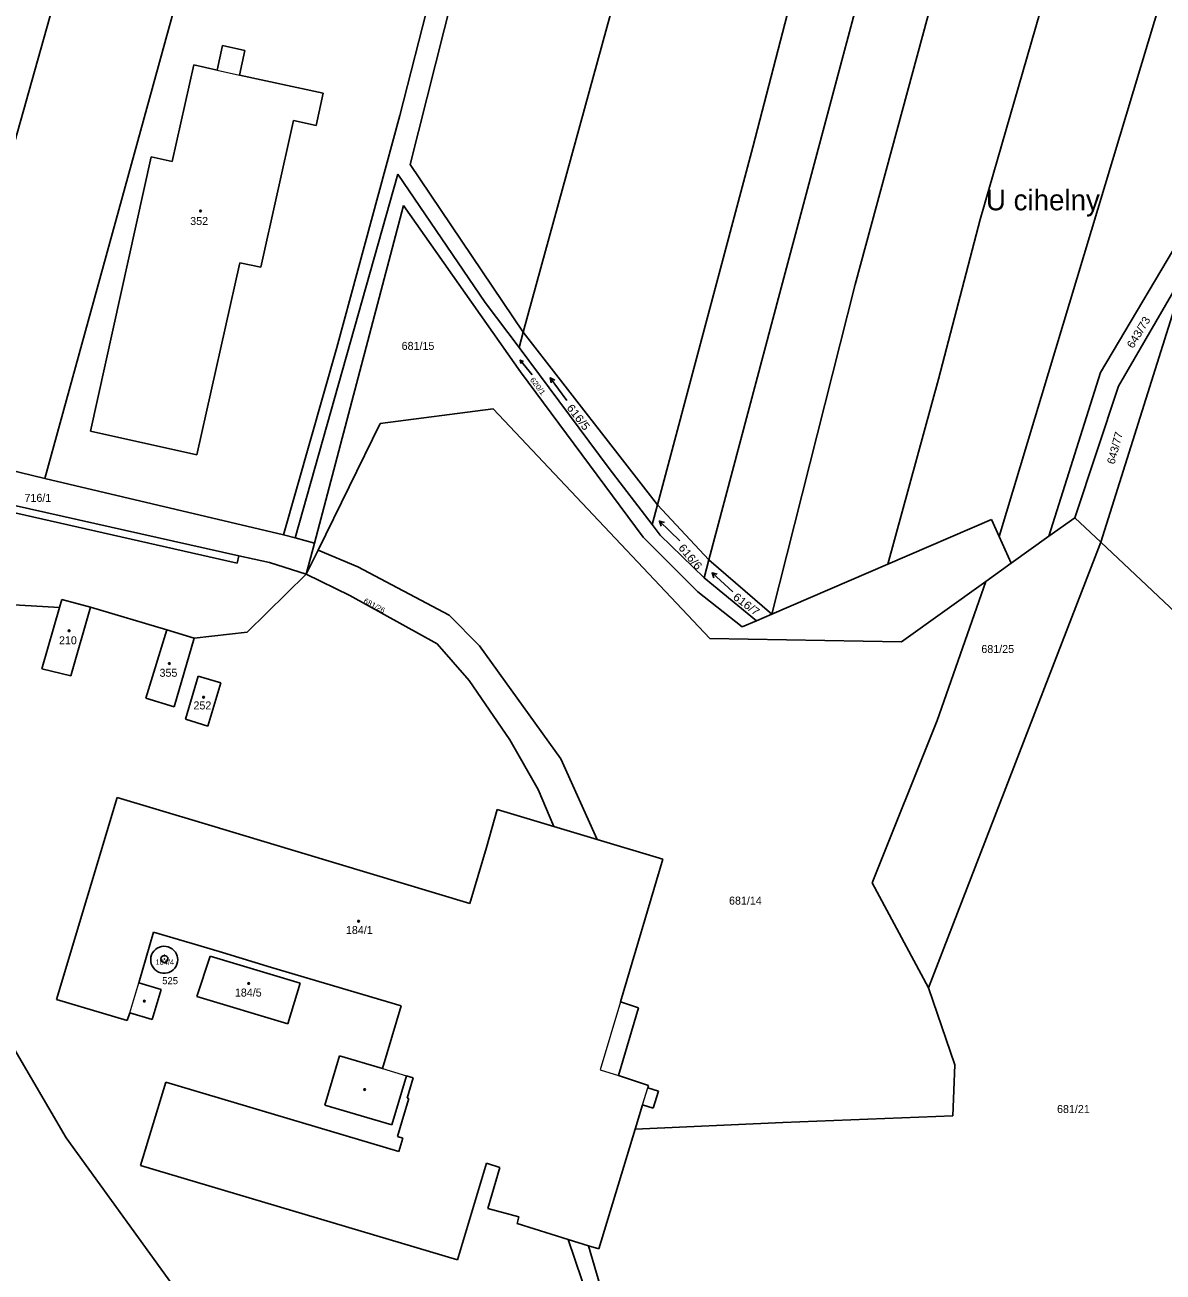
# Model space of a CAD drawing. Extents: x -701211 to -698780, y -1014269 to -1012378.
# Drawn here: x -700355.1 to -700113.3, y -1014024.8 to -1013759.8 of the extents above; entities that cross this region are included whole.
import ezdxf
from ezdxf.enums import TextEntityAlignment as Align

# ---------------------------------------------------------------- set-up
doc = ezdxf.new("R2010")
doc.units = 0
doc.header["$LTSCALE"] = 0.68
for name, color, linetype, lineweight in [('1', 7, 'Continuous', 25), ('3', 7, 'Continuous', 25), ('4', 7, 'Continuous', 13), ('5', 7, 'Continuous', 25), ('7', 7, 'Continuous', 13), ('8', 7, 'Continuous', 25)]:
    doc.layers.add(name, color=color, linetype=linetype, lineweight=lineweight)
doc.layers.add('2', color=7, linetype='Continuous')

msp = doc.modelspace()

# ---------------------------------------------------------------- linework, layer by layer
at = {"layer": '1'}
for p, q in [((-700152.11, -1013801.13), (-700103.11, -1013630.91)), ((-700375.69, -1013850.23), (-700324.49, -1013667.95)), ((-700169.53, -1013666.16), (-700200.4, -1013785.73)), ((-700300.53, -1013673.39), (-700350.86, -1013856.14)), ((-700092.33, -1013683.22), (-700148.1, -1013868.52)), ((-700275.41, -1013779.04), (-700251.21, -1013684.29)), ((-700249.19, -1013825.04), (-700213.5, -1013694.58)), ((-700273.23, -1013789.41), (-700250.03, -1013697.82)), ((-700194.71, -1013816.74), (-700166.66, -1013711.75)), ((-700178.73, -1013814.96), (-700161.98, -1013753.3)), ((-700313.1, -1013764.16), (-700314.23, -1013769.37)), ((-700308.35, -1013765.19), (-700313.1, -1013764.16)), ((-700309.49, -1013770.43), (-700308.35, -1013765.19)), ((-700319.17, -1013768.3), (-700323.76, -1013788.78)), ((-700314.23, -1013769.37), (-700319.17, -1013768.3)), ((-700291.68, -1013774.3), (-700309.49, -1013770.43)), ((-700293.21, -1013781.14), (-700291.68, -1013774.3)), ((-700288.81, -1013828.32), (-700275.41, -1013779.04)), ((-700304.97, -1013811.28), (-700298.02, -1013780.1)), ((-700298.02, -1013780.1), (-700293.21, -1013781.14)), ((-700220.71, -1013861.79), (-700200.4, -1013785.73)), ((-700328.22, -1013787.8), (-700341.16, -1013846.09)), ((-700323.76, -1013788.78), (-700328.22, -1013787.8)), ((-700249.19, -1013825.04), (-700273.23, -1013789.41)), ((-700275.83, -1013791.47), (-700297.66, -1013868.8)), ((-700275.83, -1013791.47), (-700257.26, -1013818.75)), ((-700126.55, -1013833.66), (-700102.16, -1013792.37)), ((-700293.56, -1013869.88), (-700274.66, -1013798.13)), ((-700274.66, -1013798.13), (-700249.82, -1013833.47)), ((-700160.98, -1013835.07), (-700152.11, -1013801.13)), ((-700318.53, -1013851.13), (-700309.39, -1013810.31)), ((-700309.39, -1013810.31), (-700304.97, -1013811.28)), ((-700126.53, -1013869.72), (-700108.15, -1013811.38)), ((-700122.79, -1013836.53), (-700108.15, -1013811.38)), ((-700196.42, -1013885), (-700178.73, -1013814.96)), ((-700257.26, -1013818.75), (-700250.1, -1013828.36)), ((-700209.77, -1013873.46), (-700194.71, -1013816.74)), ((-700250.1, -1013828.36), (-700249.19, -1013825.04)), ((-700249.19, -1013825.04), (-700220.71, -1013861.79)), ((-700250.1, -1013828.36), (-700230.98, -1013854.02)), ((-700249.82, -1013833.47), (-700223.72, -1013868.65)), ((-700171.79, -1013874.38), (-700160.98, -1013835.07)), ((-700137.52, -1013868.44), (-700126.55, -1013833.66)), ((-700132.06, -1013864.53), (-700122.79, -1013836.53)), ((-700255.6, -1013841.37), (-700279.57, -1013844.46)), ((-700209.56, -1013890.14), (-700255.6, -1013841.37)), ((-700292.8, -1013871.39), (-700279.57, -1013844.46)), ((-700341.16, -1013846.09), (-700318.53, -1013851.13)), ((-700350.86, -1013856.14), (-700375.69, -1013850.23)), ((-700230.98, -1013854.02), (-700221.83, -1013865.97)), ((-700374.64, -1013857.97), (-700309.64, -1013872.57)), ((-700310, -1013874.16), (-700361.05, -1013862.58)), ((-700220.71, -1013861.79), (-700221.83, -1013865.97)), ((-700220.71, -1013861.79), (-700209.77, -1013873.46)), ((-700221.83, -1013865.97), (-700220.12, -1013868.2)), ((-700149.74, -1013864.87), (-700171.79, -1013874.38)), ((-700148.1, -1013868.52), (-700149.74, -1013864.87)), ((-700132.06, -1013864.53), (-700137.52, -1013868.44)), ((-700132.06, -1013864.53), (-700126.53, -1013869.72)), ((-700300.12, -1013868.12), (-700297.66, -1013868.8)), ((-700297.66, -1013868.8), (-700293.56, -1013869.88)), ((-700223.72, -1013868.65), (-700212.15, -1013880.22)), ((-700220.12, -1013868.2), (-700210.79, -1013877.28)), ((-700145.56, -1013874.19), (-700148.1, -1013868.52)), ((-700145.56, -1013874.19), (-700137.52, -1013868.44)), ((-700295.29, -1013876.47), (-700293.56, -1013869.88)), ((-700292.8, -1013871.39), (-700295.29, -1013876.47)), ((-700292.8, -1013871.39), (-700284.36, -1013874.94)), ((-700163.11, -1013964.42), (-700126.53, -1013869.72)), ((-700109.42, -1013885.76), (-700126.53, -1013869.72)), ((-700310, -1013874.16), (-700309.64, -1013872.57)), ((-700303.08, -1013874.04), (-700309.64, -1013872.57)), ((-700295.29, -1013876.47), (-700303.08, -1013874.04)), ((-700209.77, -1013873.46), (-700210.79, -1013877.28)), ((-700209.77, -1013873.46), (-700196.42, -1013885)), ((-700171.79, -1013874.38), (-700196.42, -1013885)), ((-700150.96, -1013878.06), (-700145.56, -1013874.19)), ((-700307.85, -1013888.81), (-700295.29, -1013876.47)), ((-700295.29, -1013876.47), (-700286.04, -1013881.02)), ((-700284.36, -1013874.94), (-700264.92, -1013885.2)), ((-700210.79, -1013877.28), (-700199.69, -1013886.41)), ((-700168.85, -1013890.87), (-700150.96, -1013878.06)), ((-700150.96, -1013878.06), (-700161.28, -1013907.62)), ((-700379.57, -1013881.73), (-700347.72, -1013883.56)), ((-700347.22, -1013881.85), (-700347.72, -1013883.56)), ((-700341.12, -1013883.53), (-700347.22, -1013881.85)), ((-700267.49, -1013891.29), (-700286.04, -1013881.02)), ((-700212.15, -1013880.22), (-700202.68, -1013887.7)), ((-700347.72, -1013883.56), (-700351.49, -1013896.58)), ((-700345.28, -1013898.08), (-700341.12, -1013883.53)), ((-700341.12, -1013883.53), (-700324.93, -1013888.34)), ((-700264.92, -1013885.2), (-700258.51, -1013891.71)), ((-700196.42, -1013885), (-700199.69, -1013886.41)), ((-700199.69, -1013886.41), (-700202.68, -1013887.7)), ((-700324.93, -1013888.34), (-700329.35, -1013902.83)), ((-700319.09, -1013890.11), (-700324.93, -1013888.34)), ((-700323.37, -1013904.65), (-700319.09, -1013890.11)), ((-700319.09, -1013890.11), (-700307.85, -1013888.81)), ((-700168.85, -1013890.87), (-700209.56, -1013890.14)), ((-700260.67, -1013899.06), (-700267.49, -1013891.29)), ((-700241.19, -1013915.76), (-700258.51, -1013891.71)), ((-700351.49, -1013896.58), (-700345.28, -1013898.08)), ((-700320.98, -1013907.33), (-700318.25, -1013898.14)), ((-700313.47, -1013899.56), (-700318.25, -1013898.14)), ((-700316.22, -1013908.77), (-700313.47, -1013899.56)), ((-700252.06, -1013911.66), (-700260.67, -1013899.06)), ((-700329.35, -1013902.83), (-700323.37, -1013904.65)), ((-700320.98, -1013907.33), (-700316.22, -1013908.77)), ((-700161.28, -1013907.62), (-700175.06, -1013942.11)), ((-700246.07, -1013922.27), (-700252.06, -1013911.66)), ((-700241.19, -1013915.76), (-700233.51, -1013932.86)), ((-700242.72, -1013930.1), (-700246.07, -1013922.27)), ((-700335.47, -1013923.92), (-700348.34, -1013966.9)), ((-700335.47, -1013923.92), (-700317.48, -1013929.35)), ((-700257.03, -1013934.55), (-700254.72, -1013926.52)), ((-700254.72, -1013926.52), (-700242.72, -1013930.1)), ((-700260.53, -1013946.46), (-700317.48, -1013929.35)), ((-700242.72, -1013930.1), (-700233.51, -1013932.86)), ((-700233.51, -1013932.86), (-700219.54, -1013937.03)), ((-700257.03, -1013934.55), (-700260.53, -1013946.46)), ((-700219.54, -1013937.03), (-700228.58, -1013967.37)), ((-700175.06, -1013942.11), (-700163.11, -1013964.42)), ((-700330.9, -1013963.31), (-700327.73, -1013952.56)), ((-700318.31, -1013955.36), (-700327.73, -1013952.56)), ((-700369.62, -1013956.44), (-700346.3, -1013996.29)), ((-700327.94, -1013956.97), (-700328.15, -1013957.4)), ((-700327.67, -1013956.58), (-700327.94, -1013956.97)), ((-700327.33, -1013956.24), (-700327.67, -1013956.58)), ((-700326.94, -1013955.96), (-700327.33, -1013956.24)), ((-700326.5, -1013955.76), (-700326.94, -1013955.96)), ((-700326.04, -1013955.62), (-700326.5, -1013955.76)), ((-700325.57, -1013955.57), (-700326.04, -1013955.62)), ((-700325.09, -1013955.59), (-700325.57, -1013955.57)), ((-700324.62, -1013955.7), (-700325.09, -1013955.59)), ((-700324.18, -1013955.88), (-700324.62, -1013955.7)), ((-700323.77, -1013956.13), (-700324.18, -1013955.88)), ((-700323.41, -1013956.44), (-700323.77, -1013956.13)), ((-700323.11, -1013956.81), (-700323.41, -1013956.44)), ((-700322.87, -1013957.23), (-700323.11, -1013956.81)), ((-700313.12, -1013956.9), (-700318.31, -1013955.36)), ((-700313.12, -1013956.9), (-700302.67, -1013960.04)), ((-700328.29, -1013957.86), (-700328.35, -1013958.33)), ((-700328.35, -1013958.33), (-700328.32, -1013958.81)), ((-700328.32, -1013958.81), (-700328.22, -1013959.28)), ((-700328.15, -1013957.4), (-700328.29, -1013957.86)), ((-700328.22, -1013959.28), (-700328.04, -1013959.72)), ((-700322.96, -1013959.8), (-700322.76, -1013959.37)), ((-700322.71, -1013957.68), (-700322.87, -1013957.23)), ((-700322.76, -1013959.37), (-700322.65, -1013958.9)), ((-700322.65, -1013957.95), (-700322.71, -1013957.68)), ((-700322.61, -1013958.42), (-700322.65, -1013957.95)), ((-700322.65, -1013958.9), (-700322.61, -1013958.42)), ((-700315.74, -1013957.69), (-700318.52, -1013966.26)), ((-700296.58, -1013963.39), (-700315.74, -1013957.69)), ((-700328.04, -1013959.72), (-700327.78, -1013960.15)), ((-700327.78, -1013960.15), (-700327.46, -1013960.51)), ((-700327.46, -1013960.51), (-700327.09, -1013960.81)), ((-700327.09, -1013960.81), (-700326.67, -1013961.04)), ((-700326.67, -1013961.04), (-700326.22, -1013961.21)), ((-700326.22, -1013961.21), (-700325.75, -1013961.29)), ((-700325.75, -1013961.29), (-700325.27, -1013961.3)), ((-700325.27, -1013961.3), (-700324.8, -1013961.22)), ((-700324.8, -1013961.22), (-700324.49, -1013961.13)), ((-700324.49, -1013961.13), (-700323.92, -1013960.85)), ((-700323.92, -1013960.85), (-700323.54, -1013960.56)), ((-700323.54, -1013960.56), (-700323.22, -1013960.2)), ((-700323.22, -1013960.2), (-700322.96, -1013959.8)), ((-700302.67, -1013960.04), (-700275.14, -1013968.21)), ((-700330.9, -1013963.31), (-700326.15, -1013964.73)), ((-700328.06, -1013971.1), (-700326.15, -1013964.73)), ((-700299.21, -1013972.07), (-700296.58, -1013963.39)), ((-700157.49, -1013980.72), (-700163.11, -1013964.42)), ((-700348.34, -1013966.9), (-700333.31, -1013971.36)), ((-700318.52, -1013966.26), (-700299.21, -1013972.07)), ((-700228.58, -1013967.37), (-700224.72, -1013968.61)), ((-700333.31, -1013971.36), (-700332.81, -1013969.68)), ((-700332.81, -1013969.68), (-700328.06, -1013971.1)), ((-700275.14, -1013968.21), (-700279.1, -1013981.55)), ((-700291.33, -1013989.29), (-700288.25, -1013978.85)), ((-700288.25, -1013978.85), (-700279.1, -1013981.55)), ((-700157.49, -1013980.72), (-700157.92, -1013991.59)), ((-700274.03, -1013983.1), (-700277.1, -1013993.53)), ((-700272.61, -1013983.51), (-700274.03, -1013983.1)), ((-700273.88, -1013987.8), (-700272.61, -1013983.51)), ((-700330.5, -1014002.15), (-700325.12, -1013984.44)), ((-700325.12, -1013984.44), (-700275.65, -1013999.17)), ((-700222.59, -1013985.17), (-700222.73, -1013985.65)), ((-700222.73, -1013985.65), (-700220.49, -1013986.34)), ((-700274.66, -1013991.68), (-700273.52, -1013987.91)), ((-700273.52, -1013987.91), (-700273.88, -1013987.8)), ((-700220.49, -1013986.34), (-700221.6, -1013989.97)), ((-700277.1, -1013993.53), (-700291.33, -1013989.29)), ((-700225.41, -1013994.42), (-700223.84, -1013989.28)), ((-700221.6, -1013989.97), (-700223.84, -1013989.28)), ((-700275.92, -1013995.96), (-700274.66, -1013991.68)), ((-700194.07, -1013993.03), (-700225.41, -1013994.42)), ((-700194.07, -1013993.03), (-700157.92, -1013991.59)), ((-700346.3, -1013996.29), (-700316.48, -1014037.51)), ((-700274.77, -1013996.3), (-700275.92, -1013995.96)), ((-700275.65, -1013999.17), (-700274.77, -1013996.3)), ((-700225.41, -1013994.42), (-700233.16, -1014019.85)), ((-700256.98, -1014001.68), (-700263.18, -1014022.21)), ((-700254.19, -1014002.57), (-700256.98, -1014001.68)), ((-700263.18, -1014022.21), (-700330.5, -1014002.15)), ((-700256.75, -1014011.27), (-700254.19, -1014002.57)), ((-700250.14, -1014013.04), (-700256.75, -1014011.27)), ((-700250.53, -1014014.5), (-700250.14, -1014013.04)), ((-700239.68, -1014017.84), (-700250.53, -1014014.5)), ((-700235.33, -1014019.18), (-700239.68, -1014017.84)), ((-700227.36, -1014054.33), (-700239.68, -1014017.84)), ((-700233.16, -1014019.85), (-700235.33, -1014019.18)), ((-700235.33, -1014019.18), (-700231.73, -1014031.58))]:
    msp.add_line(p, q, dxfattribs=at)
for points in [[(-700288.81, -1013828.32), (-700300.12, -1013868.12), (-700350.86, -1013856.14)], [(-700224.72, -1013968.61), (-700229, -1013982.99), (-700222.59, -1013985.17)]]:
    msp.add_lwpolyline(points, dxfattribs=at)
at = {"layer": '3'}
for p, q in [((-700249.858, -1013831.015), (-700249.185, -1013831.313)), ((-700243.456, -1013834.744), (-700242.476, -1013835.24)), ((-700220.284, -1013865.228), (-700219.233, -1013865.546)), ((-700209.106, -1013876.235), (-700208.045, -1013876.516))]:
    msp.add_line(p, q, dxfattribs=at)
for points in [[(-700247.328, -1013834.14), (-700249.858, -1013831.015), (-700249.707, -1013831.736)], [(-700239.93, -1013839.598), (-700243.456, -1013834.744), (-700243.288, -1013835.829)], [(-700215.968, -1013869.396), (-700220.284, -1013865.228), (-700219.93, -1013866.267)], [(-700204.648, -1013880.25), (-700209.106, -1013876.235), (-700208.716, -1013877.261)]]:
    msp.add_lwpolyline(points, dxfattribs=at)
at = {"layer": '4'}
for p, q in [((-700314.23, -1013769.37), (-700309.49, -1013770.43)), ((-700332.81, -1013969.68), (-700330.9, -1013963.31)), ((-700279.1, -1013981.55), (-700274.03, -1013983.1)), ((-700223.84, -1013989.28), (-700222.73, -1013985.65))]:
    msp.add_line(p, q, dxfattribs=at)
msp.add_lwpolyline([(-700228.58, -1013967.37), (-700232.88, -1013981.81), (-700229, -1013982.99)], dxfattribs=at)
at = {"layer": '5'}
for centre, radius in [((-700317.7568, -1013799.3292), 0.175), ((-700345.6668, -1013888.5292), 0.175), ((-700324.3968, -1013895.4892), 0.175), ((-700317.1168, -1013902.6392), 0.175), ((-700284.1968, -1013950.2292), 0.175), ((-700325.4346, -1013957.5394), 0.1172), ((-700307.5468, -1013963.4592), 0.175), ((-700329.6868, -1013967.2192), 0.175), ((-700282.8768, -1013986.0092), 0.175)]:
    msp.add_circle(centre, radius, dxfattribs=at)
at = {"layer": '8'}
for radius in [0.75, 0.03]:
    msp.add_circle((-700325.43, -1013958.2698), radius, dxfattribs=at)

# ---------------------------------------------------------------- texts
at = {"layer": '2'}
for s, p in [('352', (-700319.95, -1013802.295)), ('681/15', (-700275.04, -1013828.835)), ('716/1', (-700355.15, -1013861.125)), ('210', (-700347.83, -1013891.395)), ('681/25', (-700151.89, -1013893.245)), ('355', (-700326.47, -1013898.295)), ('252', (-700319.26, -1013905.235)), ('681/14', (-700205.49, -1013946.705)), ('184/1', (-700286.87, -1013952.955)), ('184/5', (-700310.46, -1013966.245)), ('681/21', (-700135.81, -1013990.995))]:
    msp.add_text(s, height=1.7, dxfattribs=at).set_placement(p)
for s, height, rotation, width, p in [('643/73', 1.7, 59, 1.05, (-700117.7717, -1013825.5358)), ('620/1', 1.14, 307, 1.1, (-700246.5859, -1013836.8855)), ('616/5', 1.7, 308, 1.1, (-700238.1555, -1013843.6577)), ('616/6', 1.7, 310, 1.1, (-700214.3517, -1013873.3506)), ('681/26', 1.14, 332, 1.05, (-700281.0776, -1013883.6736)), ('616/7', 1.7, 323, 1.1, (-700202.3145, -1013883.5651))]:
    msp.add_text(s, height=height, rotation=rotation, dxfattribs=dict(at, width=width)).set_placement(p, align=Align.CENTER)
msp.add_text('643/77', height=1.7, rotation=75, dxfattribs=at).set_placement((-700122.7089, -1013849.898), align=Align.CENTER)
msp.add_text('184/4', height=1.14, dxfattribs=at).set_placement((-700325.349, -1013959.495), align=Align.CENTER)
at = {"layer": '7'}
msp.add_text('U cihelny', height=4.4, dxfattribs=at).set_placement((-700138.819, -1013799.18), align=Align.CENTER)
at = {"layer": '8'}
msp.add_text('525', height=1.5, dxfattribs=at).set_placement((-700322.546, -1013963.62), align=Align.RIGHT)

doc.saveas('drawing.dxf')
